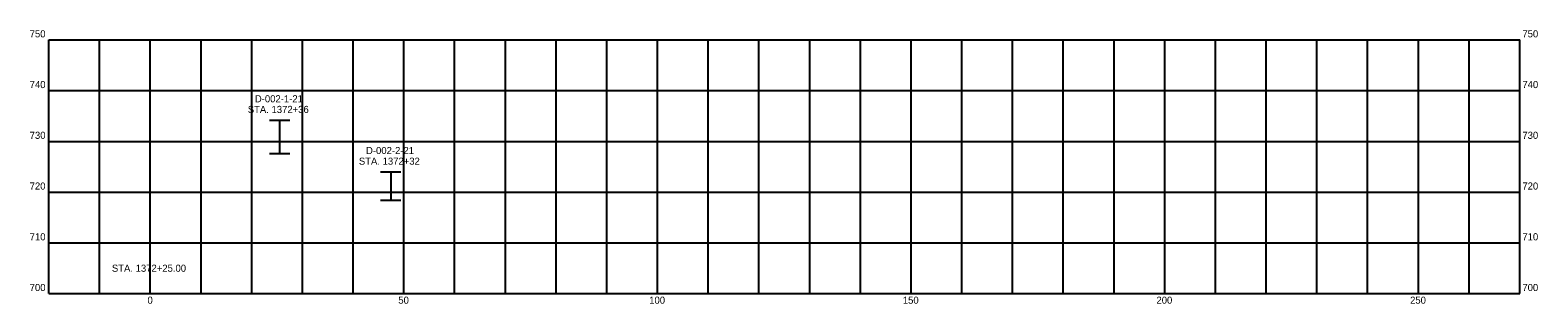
# Model space of a CAD drawing. Extents: x -24 to 274, y 698 to 752.
import ezdxf

# ---------------------------------------------------------------- set-up
doc = ezdxf.new("R2010")
doc.units = 0
for name, color, linetype in [('GE_X_Alignment_1000_Curve_Data', 7, 'Continuous'), ('GE_X_Alignment_1000_Stations', 7, 'Continuous'), ('GT_Project_Soil_Boring', 7, 'Continuous'), ('GT_Project_Text', 7, 'Continuous'), ('GT_Project_Text_3', 7, 'Continuous')]:
    doc.layers.add(name, color=color, linetype=linetype)

msp = doc.modelspace()

# ---------------------------------------------------------------- linework, layer by layer
at = {"layer": 'GE_X_Alignment_1000_Stations'}
for p, q in [((-20, 700), (-20, 750)), ((-20, 750), (270, 750)), ((-10, 700), (-10, 750)), ((0, 700), (0, 750)), ((10, 700), (10, 750)), ((20, 700), (20, 750)), ((30, 700), (30, 750)), ((40, 700), (40, 750)), ((50, 700), (50, 750)), ((60, 700), (60, 750)), ((70, 700), (70, 750)), ((80, 700), (80, 750)), ((90, 700), (90, 750)), ((100, 700), (100, 750)), ((110, 700), (110, 750)), ((120, 700), (120, 750)), ((130, 700), (130, 750)), ((140, 700), (140, 750)), ((150, 700), (150, 750)), ((160, 700), (160, 750)), ((170, 700), (170, 750)), ((180, 700), (180, 750)), ((190, 700), (190, 750)), ((200, 700), (200, 750)), ((210, 700), (210, 750)), ((220, 700), (220, 750)), ((230, 700), (230, 750)), ((240, 700), (240, 750)), ((250, 700), (250, 750)), ((260, 700), (260, 750)), ((270, 700), (270, 750)), ((-20, 740), (270, 740)), ((-20, 730), (270, 730)), ((-20, 720), (270, 720)), ((-20, 710), (270, 710)), ((-20, 700), (270, 700))]:
    msp.add_line(p, q, dxfattribs=at)
at = {"layer": 'GT_Project_Soil_Boring'}
for p, q in [((23.5, 734.2), (27.5, 734.2)), ((25.5, 734.2), (25.5, 727.64)), ((23.5, 727.64), (27.5, 727.64)), ((45.4, 724), (49.4, 724)), ((47.4, 724), (47.4, 718.42)), ((45.4, 718.42), (49.4, 718.42))]:
    msp.add_line(p, q, dxfattribs=at)

# ---------------------------------------------------------------- texts
at = {"layer": 'GE_X_Alignment_1000_Curve_Data'}
for s, p in [('750', (-23.78, 750.5)), ('750', (270.5, 750.5)), ('740', (-23.78, 740.5)), ('740', (270.5, 740.5)), ('730', (-23.78, 730.5)), ('730', (270.5, 730.5)), ('720', (-23.78, 720.5)), ('720', (270.5, 720.5)), ('710', (-23.78, 710.5)), ('710', (270.5, 710.5)), ('STA. 1372+25.00', (-7.57, 704.3)), ('700', (-23.78, 700.5)), ('700', (270.5, 700.5)), ('0', (-0.55, 698)), ('50', (48.9, 698)), ('100', (98.36, 698)), ('150', (148.36, 698)), ('200', (198.36, 698)), ('250', (248.36, 698))]:
    msp.add_text(s, height=1.4, dxfattribs=at).set_placement(p)
at = {"layer": 'GT_Project_Text'}
for s, p in [('D-002-1-21', (20.62, 737.7)), ('D-002-2-21', (42.53, 727.5))]:
    msp.add_text(s, height=1.4, dxfattribs=at).set_placement(p)
at = {"layer": 'GT_Project_Text_3'}
for s, p in [('STA. 1372+36', (19.22, 735.6)), ('STA. 1372+32', (41.12, 725.4))]:
    msp.add_text(s, height=1.4, dxfattribs=at).set_placement(p)

doc.saveas('drawing.dxf')
